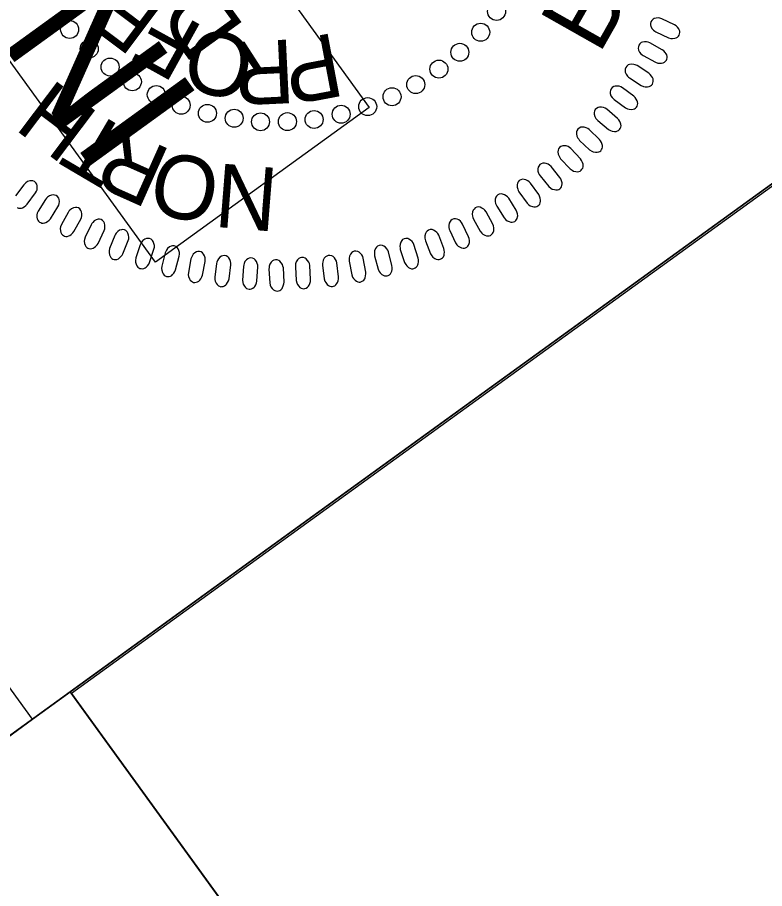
# Model space of a CAD drawing. Extents: x 474925 to 478950, y 494687 to 502905.
# Drawn here: x 475099.5 to 475166, y 502107.5 to 502185.1 of the extents above; entities that cross this region are included whole.
import ezdxf

# ---------------------------------------------------------------- set-up
doc = ezdxf.new("R2010")
doc.units = 0
for name, color, linetype in [('Prop Grid Mask', 7, 'Continuous'), ('Sheet Layout Plan Border', 7, 'Continuous'), ('Sheet PE Seal Cell', 7, 'Continuous'), ('Sheet Plan CELL', 7, 'Continuous'), ('Sheet Sticker Incomplete CELL', 7, 'Continuous')]:
    doc.layers.add(name, color=color, linetype=linetype)

msp = doc.modelspace()

# ---------------------------------------------------------------- linework, layer by layer
at = {"layer": 'Prop Grid Mask'}
msp.add_lwpolyline([(475070.393, 502100.609), (475162.685, 501973.147), (475196.466, 501997.607), (475104.174, 502125.069)], close=True, dxfattribs=at)
at = {"layer": 'Sheet Layout Plan Border'}
for points in [[(476646.384, 501714.386), (476110.18, 502454.921), (476091.748, 502441.575), (476003.493, 502563.461), (475989.428, 502553.276), (475869.086, 502719.476), (475838.053, 502697.006), (475782.546, 502773.666), (475678.649, 502698.454), (475652.98, 502679.873), (475264.351, 502398.541), (475136.14, 502305.707), (475210.951, 502202.387), (475104.173, 502125.071), (475196.466, 501997.607), (475162.674, 501973.139), (475721.996, 501200.68)], [(476646.506, 501714.234), (476022.047, 502576.655), (475989.428, 502553.276), (475869.2, 502719.318), (475838.175, 502696.853), (475782.667, 502773.513), (475678.77, 502698.302), (475653.102, 502679.72), (475264.472, 502398.389), (475136.261, 502305.554), (475211.073, 502202.234), (475104.294, 502124.918), (475196.588, 501997.455), (475162.795, 501972.986), (475722.117, 501200.527)]]:
    msp.add_lwpolyline(points, close=True, dxfattribs=at)
at = {"layer": 'Sheet PE Seal Cell'}
for points in [[(475156.336, 502183.846), (475157.445, 502183.321), (475157.659, 502183.262), (475157.808, 502183.249), (475158.009, 502183.277), (475158.15, 502183.319), (475158.27, 502183.386), (475158.351, 502183.464), (475158.417, 502183.557), (475158.446, 502183.666), (475158.47, 502183.788), (475158.461, 502183.907), (475158.416, 502184.045), (475158.369, 502184.133), (475158.263, 502184.258), (475158.126, 502184.388), (475157.992, 502184.477), (475156.859, 502185.021), (475156.695, 502185.073), (475156.55, 502185.092), (475156.368, 502185.079), (475156.194, 502185.038), (475156.08, 502184.984), (475155.959, 502184.868), (475155.877, 502184.74), (475155.849, 502184.589), (475155.849, 502184.473), (475155.885, 502184.315), (475155.988, 502184.135), (475156.121, 502183.997), (475156.225, 502183.915)], [(475155.21, 502181.737), (475156.284, 502181.144), (475156.494, 502181.071), (475156.642, 502181.049), (475156.844, 502181.066), (475156.987, 502181.098), (475157.111, 502181.157), (475157.197, 502181.229), (475157.269, 502181.318), (475157.305, 502181.426), (475157.336, 502181.545), (475157.335, 502181.665), (475157.298, 502181.805), (475157.258, 502181.896), (475157.159, 502182.027), (475157.03, 502182.166), (475156.902, 502182.263), (475155.805, 502182.878), (475155.646, 502182.94), (475155.502, 502182.968), (475155.32, 502182.967), (475155.143, 502182.937), (475155.026, 502182.89), (475154.897, 502182.781), (475154.807, 502182.659), (475154.771, 502182.51), (475154.764, 502182.393), (475154.789, 502182.234), (475154.88, 502182.048), (475155.005, 502181.902), (475155.104, 502181.813)], [(475153.988, 502179.743), (475155.023, 502179.083), (475155.229, 502178.996), (475155.374, 502178.965), (475155.577, 502178.969), (475155.722, 502178.992), (475155.85, 502179.044), (475155.939, 502179.11), (475156.017, 502179.194), (475156.06, 502179.299), (475156.099, 502179.416), (475156.105, 502179.536), (475156.077, 502179.678), (475156.042, 502179.772), (475155.952, 502179.909), (475155.832, 502180.056), (475155.71, 502180.161), (475154.655, 502180.843), (475154.499, 502180.915), (475154.358, 502180.952), (475154.175, 502180.962), (475153.997, 502180.942), (475153.877, 502180.903), (475153.742, 502180.803), (475153.645, 502180.687), (475153.599, 502180.541), (475153.584, 502180.425), (475153.6, 502180.264), (475153.679, 502180.073), (475153.794, 502179.919), (475153.888, 502179.825)], [(475152.621, 502177.816), (475153.613, 502177.093), (475153.812, 502176.994), (475153.955, 502176.953), (475154.159, 502176.944), (475154.305, 502176.958), (475154.435, 502177.002), (475154.529, 502177.063), (475154.611, 502177.141), (475154.66, 502177.244), (475154.707, 502177.358), (475154.721, 502177.478), (475154.701, 502177.621), (475154.673, 502177.716), (475154.591, 502177.859), (475154.481, 502178.013), (475154.366, 502178.125), (475153.355, 502178.872), (475153.205, 502178.953), (475153.065, 502179), (475152.884, 502179.021), (475152.705, 502179.013), (475152.583, 502178.982), (475152.442, 502178.89), (475152.338, 502178.781), (475152.282, 502178.637), (475152.261, 502178.523), (475152.266, 502178.362), (475152.333, 502178.165), (475152.438, 502178.005), (475152.526, 502177.904)], [(475151.155, 502175.947), (475152.099, 502175.163), (475152.291, 502175.052), (475152.432, 502175.002), (475152.634, 502174.98), (475152.781, 502174.985), (475152.914, 502175.021), (475153.011, 502175.076), (475153.098, 502175.149), (475153.154, 502175.248), (475153.208, 502175.359), (475153.229, 502175.477), (475153.219, 502175.622), (475153.196, 502175.719), (475153.124, 502175.866), (475153.024, 502176.027), (475152.915, 502176.146), (475151.954, 502176.955), (475151.809, 502177.046), (475151.673, 502177.1), (475151.493, 502177.133), (475151.314, 502177.137), (475151.191, 502177.113), (475151.044, 502177.03), (475150.933, 502176.928), (475150.868, 502176.787), (475150.84, 502176.675), (475150.835, 502176.513), (475150.889, 502176.314), (475150.984, 502176.146), (475151.065, 502176.041)], [(475149.54, 502174.185), (475150.433, 502173.344), (475150.618, 502173.22), (475150.755, 502173.162), (475150.956, 502173.128), (475151.102, 502173.123), (475151.237, 502173.15), (475151.338, 502173.199), (475151.429, 502173.267), (475151.491, 502173.362), (475151.552, 502173.47), (475151.581, 502173.587), (475151.579, 502173.732), (475151.563, 502173.83), (475151.5, 502173.982), (475151.41, 502174.148), (475151.31, 502174.274), (475150.4, 502175.141), (475150.261, 502175.241), (475150.129, 502175.304), (475149.952, 502175.348), (475149.773, 502175.363), (475149.648, 502175.347), (475149.497, 502175.274), (475149.38, 502175.178), (475149.307, 502175.042), (475149.271, 502174.932), (475149.256, 502174.771), (475149.298, 502174.568), (475149.382, 502174.395), (475149.456, 502174.285)], [(475147.852, 502172.551), (475148.69, 502171.655), (475148.867, 502171.521), (475149.001, 502171.454), (475149.199, 502171.407), (475149.345, 502171.394), (475149.481, 502171.412), (475149.584, 502171.454), (475149.68, 502171.517), (475149.748, 502171.608), (475149.815, 502171.711), (475149.851, 502171.826), (475149.859, 502171.971), (475149.848, 502172.07), (475149.795, 502172.225), (475149.716, 502172.397), (475149.624, 502172.529), (475148.771, 502173.452), (475148.639, 502173.56), (475148.51, 502173.631), (475148.336, 502173.687), (475148.159, 502173.712), (475148.033, 502173.704), (475147.878, 502173.64), (475147.755, 502173.553), (475147.673, 502173.422), (475147.631, 502173.314), (475147.605, 502173.154), (475147.634, 502172.949), (475147.708, 502172.772), (475147.775, 502172.656)], [(475146.02, 502171.022), (475146.8, 502170.075), (475146.968, 502169.929), (475147.097, 502169.854), (475147.292, 502169.795), (475147.437, 502169.772), (475147.574, 502169.782), (475147.68, 502169.818), (475147.78, 502169.874), (475147.853, 502169.96), (475147.926, 502170.06), (475147.969, 502170.172), (475147.986, 502170.316), (475147.982, 502170.415), (475147.939, 502170.573), (475147.871, 502170.75), (475147.787, 502170.887), (475146.993, 502171.862), (475146.868, 502171.979), (475146.745, 502172.057), (475146.574, 502172.124), (475146.399, 502172.16), (475146.273, 502172.161), (475146.114, 502172.107), (475145.986, 502172.027), (475145.896, 502171.901), (475145.846, 502171.796), (475145.812, 502171.638), (475145.827, 502171.432), (475145.89, 502171.25), (475145.949, 502171.131)], [(475144.141, 502169.597), (475144.86, 502168.603), (475145.019, 502168.447), (475145.143, 502168.364), (475145.334, 502168.293), (475145.477, 502168.261), (475145.615, 502168.262), (475145.722, 502168.291), (475145.825, 502168.341), (475145.904, 502168.422), (475145.983, 502168.517), (475146.033, 502168.626), (475146.059, 502168.769), (475146.061, 502168.868), (475146.028, 502169.029), (475145.971, 502169.21), (475145.896, 502169.352), (475145.165, 502170.375), (475145.048, 502170.499), (475144.929, 502170.585), (475144.763, 502170.662), (475144.591, 502170.709), (475144.465, 502170.717), (475144.303, 502170.674), (475144.17, 502170.602), (475144.073, 502170.482), (475144.017, 502170.38), (475143.972, 502170.225), (475143.975, 502170.018), (475144.026, 502169.833), (475144.077, 502169.71)], [(475101.988, 502168.929), (475101.329, 502167.894), (475101.243, 502167.689), (475101.211, 502167.544), (475101.215, 502167.34), (475101.238, 502167.196), (475101.289, 502167.068), (475101.356, 502166.978), (475101.44, 502166.902), (475101.546, 502166.858), (475101.662, 502166.819), (475101.783, 502166.813), (475101.925, 502166.84), (475102.018, 502166.876), (475102.155, 502166.966), (475102.302, 502167.085), (475102.407, 502167.207), (475103.088, 502168.263), (475103.16, 502168.418), (475103.197, 502168.56), (475103.208, 502168.743), (475103.188, 502168.921), (475103.15, 502169.04), (475103.049, 502169.175), (475102.933, 502169.272), (475102.786, 502169.319), (475102.671, 502169.333), (475102.51, 502169.317), (475102.318, 502169.239), (475102.165, 502169.123), (475102.07, 502169.03)], [(475142.161, 502168.323), (475142.816, 502167.286), (475142.965, 502167.12), (475143.084, 502167.03), (475143.269, 502166.947), (475143.41, 502166.905), (475143.547, 502166.898), (475143.657, 502166.921), (475143.763, 502166.964), (475143.846, 502167.041), (475143.932, 502167.13), (475143.988, 502167.236), (475144.023, 502167.376), (475144.031, 502167.476), (475144.008, 502167.638), (475143.963, 502167.822), (475143.897, 502167.969), (475143.232, 502169.035), (475143.122, 502169.167), (475143.01, 502169.26), (475142.848, 502169.347), (475142.68, 502169.406), (475142.555, 502169.421), (475142.39, 502169.388), (475142.253, 502169.325), (475142.148, 502169.211), (475142.086, 502169.113), (475142.031, 502168.961), (475142.021, 502168.754), (475142.06, 502168.566), (475142.105, 502168.441)], [(475103.986, 502167.761), (475103.392, 502166.687), (475103.319, 502166.477), (475103.297, 502166.329), (475103.313, 502166.127), (475103.346, 502165.984), (475103.405, 502165.86), (475103.477, 502165.774), (475103.566, 502165.703), (475103.674, 502165.666), (475103.793, 502165.634), (475103.913, 502165.636), (475104.053, 502165.673), (475104.144, 502165.714), (475104.275, 502165.812), (475104.415, 502165.941), (475104.511, 502166.069), (475105.125, 502167.165), (475105.188, 502167.325), (475105.216, 502167.469), (475105.214, 502167.652), (475105.184, 502167.829), (475105.137, 502167.945), (475105.029, 502168.073), (475104.908, 502168.163), (475104.757, 502168.2), (475104.642, 502168.207), (475104.482, 502168.182), (475104.296, 502168.091), (475104.15, 502167.966), (475104.061, 502167.867)], [(475140.094, 502167.181), (475140.683, 502166.104), (475140.821, 502165.93), (475140.934, 502165.832), (475141.114, 502165.737), (475141.252, 502165.687), (475141.389, 502165.671), (475141.499, 502165.687), (475141.608, 502165.723), (475141.696, 502165.794), (475141.787, 502165.878), (475141.85, 502165.981), (475141.893, 502166.119), (475141.908, 502166.217), (475141.895, 502166.381), (475141.861, 502166.567), (475141.804, 502166.718), (475141.208, 502167.824), (475141.106, 502167.962), (475141, 502168.062), (475140.845, 502168.159), (475140.68, 502168.228), (475140.556, 502168.251), (475140.39, 502168.229), (475140.248, 502168.174), (475140.137, 502168.068), (475140.069, 502167.974), (475140.005, 502167.825), (475139.982, 502167.619), (475140.009, 502167.429), (475140.045, 502167.301)], [(475106.029, 502166.669), (475105.504, 502165.559), (475105.444, 502165.345), (475105.431, 502165.197), (475105.46, 502164.995), (475105.501, 502164.855), (475105.568, 502164.735), (475105.646, 502164.654), (475105.739, 502164.588), (475105.848, 502164.558), (475105.97, 502164.534), (475106.09, 502164.543), (475106.227, 502164.589), (475106.315, 502164.635), (475106.44, 502164.741), (475106.571, 502164.879), (475106.659, 502165.013), (475107.203, 502166.146), (475107.256, 502166.308), (475107.274, 502166.454), (475107.262, 502166.636), (475107.22, 502166.811), (475107.167, 502166.924), (475107.05, 502167.046), (475106.924, 502167.127), (475106.771, 502167.156), (475106.655, 502167.155), (475106.498, 502167.119), (475106.317, 502167.017), (475106.179, 502166.884), (475106.097, 502166.779)], [(475137.973, 502166.164), (475138.493, 502165.053), (475138.62, 502164.87), (475138.726, 502164.765), (475138.901, 502164.659), (475139.035, 502164.601), (475139.171, 502164.577), (475139.282, 502164.585), (475139.392, 502164.614), (475139.484, 502164.68), (475139.58, 502164.758), (475139.65, 502164.856), (475139.702, 502164.991), (475139.723, 502165.088), (475139.721, 502165.253), (475139.698, 502165.441), (475139.651, 502165.594), (475139.125, 502166.736), (475139.032, 502166.88), (475138.932, 502166.987), (475138.784, 502167.094), (475138.623, 502167.173), (475138.501, 502167.204), (475138.334, 502167.191), (475138.19, 502167.146), (475138.071, 502167.046), (475137.998, 502166.957), (475137.925, 502166.813), (475137.888, 502166.609), (475137.904, 502166.417), (475137.932, 502166.287)], [(475108.137, 502165.704), (475107.683, 502164.565), (475107.636, 502164.347), (475107.633, 502164.198), (475107.674, 502163.999), (475107.724, 502163.861), (475107.799, 502163.746), (475107.881, 502163.67), (475107.978, 502163.61), (475108.09, 502163.586), (475108.212, 502163.57), (475108.331, 502163.587), (475108.465, 502163.641), (475108.55, 502163.693), (475108.669, 502163.807), (475108.79, 502163.952), (475108.871, 502164.092), (475109.342, 502165.257), (475109.384, 502165.422), (475109.394, 502165.569), (475109.369, 502165.75), (475109.317, 502165.921), (475109.257, 502166.031), (475109.132, 502166.145), (475109.001, 502166.219), (475108.847, 502166.237), (475108.732, 502166.229), (475108.577, 502166.184), (475108.403, 502166.07), (475108.274, 502165.928), (475108.198, 502165.819)], [(475135.814, 502165.232), (475136.264, 502164.09), (475136.379, 502163.9), (475136.478, 502163.788), (475136.645, 502163.672), (475136.775, 502163.605), (475136.909, 502163.572), (475137.021, 502163.574), (475137.133, 502163.596), (475137.229, 502163.655), (475137.33, 502163.727), (475137.406, 502163.821), (475137.466, 502163.952), (475137.493, 502164.048), (475137.501, 502164.213), (475137.49, 502164.401), (475137.453, 502164.558), (475137, 502165.73), (475136.916, 502165.88), (475136.824, 502165.993), (475136.682, 502166.108), (475136.527, 502166.197), (475136.407, 502166.236), (475136.238, 502166.234), (475136.092, 502166.198), (475135.968, 502166.106), (475135.889, 502166.021), (475135.807, 502165.882), (475135.758, 502165.681), (475135.761, 502165.489), (475135.781, 502165.357)], [(475110.407, 502164.878), (475110.026, 502163.712), (475109.993, 502163.492), (475109.999, 502163.343), (475110.053, 502163.147), (475110.112, 502163.013), (475110.193, 502162.902), (475110.28, 502162.831), (475110.381, 502162.778), (475110.493, 502162.762), (475110.616, 502162.753), (475110.734, 502162.777), (475110.865, 502162.84), (475110.946, 502162.897), (475111.057, 502163.019), (475111.17, 502163.17), (475111.24, 502163.315), (475111.638, 502164.507), (475111.67, 502164.675), (475111.671, 502164.822), (475111.635, 502165.001), (475111.572, 502165.169), (475111.504, 502165.275), (475111.373, 502165.38), (475111.238, 502165.446), (475111.083, 502165.454), (475110.969, 502165.44), (475110.816, 502165.385), (475110.65, 502165.26), (475110.53, 502165.111), (475110.461, 502164.997)], [(475133.574, 502164.479), (475133.951, 502163.312), (475134.054, 502163.115), (475134.146, 502162.997), (475134.305, 502162.87), (475134.432, 502162.796), (475134.563, 502162.755), (475134.674, 502162.749), (475134.787, 502162.765), (475134.888, 502162.818), (475134.992, 502162.883), (475135.073, 502162.972), (475135.143, 502163.099), (475135.175, 502163.194), (475135.193, 502163.357), (475135.195, 502163.545), (475135.167, 502163.704), (475134.789, 502164.903), (475134.715, 502165.057), (475134.629, 502165.176), (475134.495, 502165.3), (475134.345, 502165.398), (475134.228, 502165.445), (475134.061, 502165.454), (475133.912, 502165.427), (475133.782, 502165.342), (475133.698, 502165.263), (475133.607, 502165.129), (475133.546, 502164.931), (475133.537, 502164.739), (475133.548, 502164.607)], [(475112.635, 502164.17), (475112.328, 502162.982), (475112.309, 502162.761), (475112.324, 502162.612), (475112.391, 502162.42), (475112.457, 502162.29), (475112.545, 502162.184), (475112.637, 502162.12), (475112.741, 502162.072), (475112.854, 502162.063), (475112.977, 502162.062), (475113.094, 502162.093), (475113.22, 502162.164), (475113.298, 502162.226), (475113.401, 502162.355), (475113.504, 502162.513), (475113.566, 502162.662), (475113.888, 502163.876), (475113.908, 502164.046), (475113.899, 502164.193), (475113.853, 502164.369), (475113.779, 502164.533), (475113.705, 502164.635), (475113.568, 502164.732), (475113.428, 502164.788), (475113.274, 502164.787), (475113.16, 502164.765), (475113.012, 502164.701), (475112.854, 502164.566), (475112.744, 502164.409), (475112.682, 502164.291)], [(475129.02, 502163.423), (475129.248, 502162.217), (475129.325, 502162.008), (475129.402, 502161.881), (475129.544, 502161.735), (475129.66, 502161.645), (475129.785, 502161.588), (475129.895, 502161.568), (475130.009, 502161.569), (475130.115, 502161.61), (475130.227, 502161.662), (475130.319, 502161.739), (475130.403, 502161.857), (475130.447, 502161.946), (475130.485, 502162.106), (475130.511, 502162.294), (475130.504, 502162.454), (475130.278, 502163.691), (475130.224, 502163.853), (475130.154, 502163.981), (475130.037, 502164.122), (475129.9, 502164.238), (475129.79, 502164.299), (475129.625, 502164.329), (475129.474, 502164.32), (475129.335, 502164.253), (475129.241, 502164.185), (475129.135, 502164.063), (475129.048, 502163.875), (475129.016, 502163.686), (475129.011, 502163.553)], [(475131.287, 502163.904), (475131.59, 502162.716), (475131.68, 502162.513), (475131.765, 502162.39), (475131.916, 502162.253), (475132.037, 502162.171), (475132.165, 502162.122), (475132.277, 502162.109), (475132.391, 502162.117), (475132.494, 502162.164), (475132.603, 502162.223), (475132.689, 502162.306), (475132.766, 502162.429), (475132.805, 502162.521), (475132.833, 502162.683), (475132.846, 502162.871), (475132.829, 502163.031), (475132.526, 502164.251), (475132.462, 502164.409), (475132.384, 502164.534), (475132.258, 502164.666), (475132.115, 502164.774), (475132.001, 502164.827), (475131.834, 502164.847), (475131.685, 502164.829), (475131.55, 502164.754), (475131.46, 502164.679), (475131.361, 502164.551), (475131.288, 502164.358), (475131.267, 502164.167), (475131.27, 502164.033)], [(475114.93, 502163.624), (475114.698, 502162.42), (475114.693, 502162.197), (475114.717, 502162.05), (475114.796, 502161.862), (475114.87, 502161.737), (475114.965, 502161.637), (475115.061, 502161.578), (475115.167, 502161.537), (475115.281, 502161.535), (475115.404, 502161.542), (475115.518, 502161.581), (475115.64, 502161.659), (475115.714, 502161.726), (475115.808, 502161.86), (475115.9, 502162.025), (475115.953, 502162.177), (475116.198, 502163.41), (475116.208, 502163.581), (475116.19, 502163.726), (475116.132, 502163.9), (475116.049, 502164.059), (475115.969, 502164.156), (475115.826, 502164.244), (475115.682, 502164.292), (475115.528, 502164.28), (475115.416, 502164.252), (475115.272, 502164.178), (475115.123, 502164.035), (475115.023, 502163.87), (475114.969, 502163.749)], [(475117.208, 502163.222), (475117.052, 502162.005), (475117.061, 502161.783), (475117.095, 502161.638), (475117.185, 502161.455), (475117.267, 502161.334), (475117.369, 502161.24), (475117.467, 502161.188), (475117.576, 502161.154), (475117.689, 502161.159), (475117.812, 502161.174), (475117.923, 502161.219), (475118.04, 502161.305), (475118.109, 502161.377), (475118.196, 502161.516), (475118.277, 502161.687), (475118.321, 502161.842), (475118.488, 502163.088), (475118.487, 502163.258), (475118.46, 502163.403), (475118.391, 502163.573), (475118.298, 502163.725), (475118.212, 502163.817), (475118.064, 502163.896), (475117.918, 502163.935), (475117.765, 502163.914), (475117.655, 502163.878), (475117.515, 502163.796), (475117.375, 502163.643), (475117.286, 502163.473), (475117.24, 502163.349)], [(475119.602, 502162.963), (475119.522, 502161.739), (475119.546, 502161.517), (475119.588, 502161.375), (475119.689, 502161.198), (475119.779, 502161.083), (475119.886, 502160.996), (475119.988, 502160.95), (475120.099, 502160.922), (475120.212, 502160.935), (475120.333, 502160.957), (475120.441, 502161.009), (475120.552, 502161.102), (475120.617, 502161.178), (475120.694, 502161.323), (475120.766, 502161.499), (475120.798, 502161.656), (475120.887, 502162.91), (475120.875, 502163.08), (475120.839, 502163.222), (475120.76, 502163.388), (475120.658, 502163.534), (475120.565, 502163.62), (475120.413, 502163.69), (475120.265, 502163.719), (475120.113, 502163.689), (475120.006, 502163.646), (475119.872, 502163.555), (475119.742, 502163.394), (475119.663, 502163.219), (475119.625, 502163.091)], [(475121.875, 502162.726), (475121.939, 502161.502), (475121.989, 502161.284), (475122.048, 502161.148), (475122.169, 502160.984), (475122.272, 502160.88), (475122.388, 502160.807), (475122.494, 502160.772), (475122.608, 502160.758), (475122.719, 502160.784), (475122.836, 502160.821), (475122.938, 502160.885), (475123.037, 502160.99), (475123.093, 502161.073), (475123.152, 502161.226), (475123.202, 502161.409), (475123.216, 502161.569), (475123.157, 502162.824), (475123.126, 502162.993), (475123.073, 502163.13), (475122.975, 502163.284), (475122.856, 502163.417), (475122.754, 502163.492), (475122.595, 502163.543), (475122.445, 502163.556), (475122.297, 502163.508), (475122.195, 502163.452), (475122.074, 502163.346), (475121.963, 502163.171), (475121.905, 502162.988), (475121.883, 502162.857)], [(475124.225, 502162.929), (475124.3, 502161.705), (475124.351, 502161.488), (475124.411, 502161.352), (475124.533, 502161.189), (475124.637, 502161.086), (475124.754, 502161.013), (475124.861, 502160.98), (475124.974, 502160.966), (475125.085, 502160.993), (475125.202, 502161.031), (475125.303, 502161.096), (475125.401, 502161.202), (475125.457, 502161.286), (475125.515, 502161.44), (475125.563, 502161.622), (475125.576, 502161.782), (475125.507, 502163.037), (475125.474, 502163.205), (475125.421, 502163.342), (475125.322, 502163.495), (475125.201, 502163.628), (475125.099, 502163.702), (475124.939, 502163.752), (475124.788, 502163.763), (475124.642, 502163.714), (475124.54, 502163.658), (475124.419, 502163.55), (475124.311, 502163.374), (475124.254, 502163.191), (475124.232, 502163.059)], [(475126.65, 502163.075), (475126.801, 502161.858), (475126.865, 502161.645), (475126.934, 502161.512), (475127.066, 502161.358), (475127.177, 502161.261), (475127.297, 502161.196), (475127.406, 502161.169), (475127.52, 502161.163), (475127.628, 502161.197), (475127.744, 502161.241), (475127.84, 502161.313), (475127.931, 502161.425), (475127.981, 502161.512), (475128.03, 502161.669), (475128.067, 502161.854), (475128.069, 502162.016), (475127.921, 502163.263), (475127.879, 502163.429), (475127.816, 502163.562), (475127.708, 502163.709), (475127.579, 502163.834), (475127.473, 502163.901), (475127.31, 502163.941), (475127.159, 502163.942), (475127.016, 502163.884), (475126.918, 502163.822), (475126.804, 502163.707), (475126.707, 502163.525), (475126.662, 502163.338), (475126.648, 502163.206)]]:
    msp.add_lwpolyline(points, close=True, dxfattribs=at)
msp.add_lwpolyline([(475099.464, 502168.193), (475099.578, 502168.147), (475099.698, 502168.134), (475099.841, 502168.152), (475099.937, 502168.182), (475100.08, 502168.263), (475100.233, 502168.373), (475100.346, 502168.489), (475101.092, 502169.499), (475101.174, 502169.649), (475101.22, 502169.789), (475101.242, 502169.97), (475101.233, 502170.149), (475101.202, 502170.271), (475101.11, 502170.412), (475101.001, 502170.516), (475100.857, 502170.572), (475100.743, 502170.593), (475100.582, 502170.588), (475100.385, 502170.521), (475100.225, 502170.416), (475100.124, 502170.329), (475100.036, 502170.233), (475099.313, 502169.242)], dxfattribs=at)
for centre in [(475142.141, 502185.67), (475104.126, 502184.062), (475140.731, 502183.813), (475105.873, 502182.328), (475138.875, 502182.028), (475107.725, 502180.719), (475137.009, 502180.531), (475109.71, 502179.403), (475134.948, 502179.157), (475111.844, 502178.264), (475132.834, 502178.07), (475114.058, 502177.311), (475130.667, 502177.19), (475116.396, 502176.594), (475118.779, 502176.156), (475125.891, 502176.044), (475128.305, 502176.513), (475121.123, 502175.838), (475123.522, 502175.853)]:
    msp.add_circle(centre, 0.801, dxfattribs=at)
at = {"layer": 'Sheet Plan CELL'}
msp.add_line((475090.699, 502115.3), (475100.814, 502122.623), dxfattribs=at)
for points in [[(476683.281, 501663.491), (475832.823, 501047.663), (475070.379, 502100.597), (475191.917, 502188.605), (475074.61, 502350.635), (475803.528, 502878.428)], [(475100.814, 502122.623), (475042.137, 502203.66), (475133.268, 502269.646), (475191.917, 502188.605)]]:
    msp.add_lwpolyline(points, close=True, dxfattribs=at)
at = {"layer": 'Sheet Sticker Incomplete CELL'}
msp.add_lwpolyline([(475130.803, 502177.117), (475111.769, 502163.335), (475025.557, 502282.4), (475044.591, 502296.182)], close=True, dxfattribs=at)

# ---------------------------------------------------------------- texts
at = {"layer": 'Sheet PE Seal Cell'}
for s, height, rotation, p in [('E', 5.669, 143.07604, (475112.989, 502186.081)), ('B', 6.236, 60.49712, (475151.256, 502181.742)), ('F', 5.669, 151.01584, (475116.223, 502184.237)), ('O', 5.669, 166.89544, (475120.933, 502183.083)), ('R', 5.669, 182.77503, (475124.001, 502183.188)), ('P', 5.669, 190.71483, (475127.713, 502183.794)), ('H', 5.669, 142.96317, (475106.889, 502176.483)), ('T', 5.669, 149.45252, (475109.896, 502174.735)), ('R', 5.669, 155.94188, (475113.339, 502173.252)), ('O', 5.669, 168.92059, (475117.83, 502172.213)), ('N', 5.669, 175.40995, (475122.834, 502171.704))]:
    msp.add_text(s, height=height, rotation=rotation, dxfattribs=at).set_placement(p)
at = {"layer": 'Sheet Sticker Incomplete CELL'}
for s, height, p in [('INCOMPLETE PLANS', 11.52, (475116.078, 502177.504)), ('DO NOT USE FOR R/W ACQUISITION', 5.76, (475119.801, 502184.213))]:
    msp.add_text(s, height=height, rotation=125.90742, dxfattribs=at).set_placement(p)

doc.saveas('drawing.dxf')
